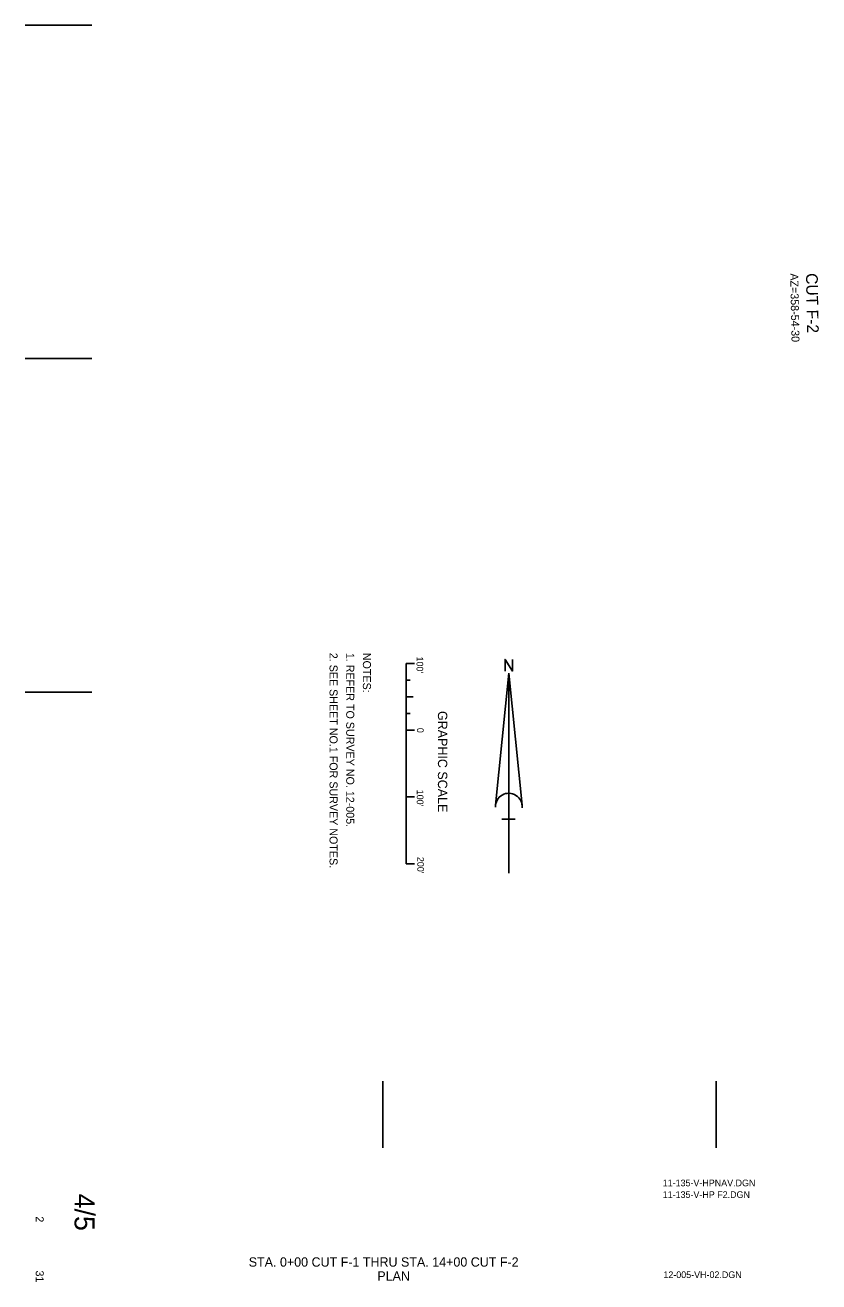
# Model space of a CAD drawing. Extents: x 585464 to 588664, y 1935616 to 1939717.
# Drawn here: x 585464 to 586654, y 1935616 to 1937500 of the extents above; entities that cross this region are included whole.
import ezdxf

# ---------------------------------------------------------------- set-up
doc = ezdxf.new("R2010")
doc.units = 0
for name, color, linetype in [('V-ANNO-DIMS', 7, 'Continuous'), ('V-ANNO-SYMB', 7, 'Continuous'), ('V-ANNO-TEXT', 7, 'Continuous'), ('V-DUCT-MULT', 7, 'Continuous'), ('V-DUCT-MULT-IDEN', 7, 'Continuous')]:
    doc.layers.add(name, color=color, linetype=linetype)

msp = doc.modelspace()

# ---------------------------------------------------------------- linework, layer by layer
at = {"layer": 'V-ANNO-TEXT'}
for p, q in [((585463.7, 1937500), (585563.7, 1937500)), ((585463.7, 1937000), (585563.7, 1937000)), ((585463.7, 1936500), (585563.7, 1936500)), ((586000, 1935917.1), (586000, 1935817.1)), ((586500, 1935917.1), (586500, 1935817.1))]:
    msp.add_line(p, q, dxfattribs=at)
at = {"layer": 'V-DUCT-MULT'}
for p, q in [((586035.3, 1936543), (586035.3, 1936242.9)), ((586035.3, 1936543), (586047.8, 1936542.9)), ((586035.6, 1936518), (586041.3, 1936517.9)), ((586169.1, 1936330.5), (586189, 1936528.5)), ((586189, 1936228.5), (586189, 1936528.5)), ((586208.9, 1936330.5), (586189, 1936528.5)), ((586035.3, 1936493), (586045.5, 1936492.9)), ((586035.6, 1936493), (586041.3, 1936493)), ((586035.6, 1936467.9), (586041.3, 1936467.9)), ((586035.3, 1936442.9), (586047.8, 1936443)), ((586035.3, 1936442.9), (586047.8, 1936443)), ((586035.3, 1936442.9), (586041.3, 1936442.9)), ((586035.3, 1936342.9), (586047.8, 1936342.9)), ((586198.5, 1936309.5), (586178.5, 1936309.5)), ((586035.3, 1936242.9), (586047.8, 1936242.9))]:
    msp.add_line(p, q, dxfattribs=at)
msp.add_lwpolyline([(586183.5, 1936531.7), (586183.5, 1936549.2), (586194.4, 1936531.7), (586194.4, 1936549.2)], dxfattribs=at)
msp.add_arc((586189, 1936328.5), 20, 355.2984, 182.0673, dxfattribs=at)

# ---------------------------------------------------------------- texts
at = {"layer": 'V-ANNO-DIMS'}
for s, height, rotation, p in [('11-135-V-HPNAV.DGN                  ', 10, 360, (586419.8, 1935759.3)), (' 4/5  ', 30, 270, (585537.8, 1935759.4)), ('11-135-V-HP F2.DGN                  ', 10, 360, (586419.8, 1935741.8)), ('  2 ', 12, 270, (585479.6, 1935723.1)), ('       STA. 0+00 CUT F-1 THRU STA. 14+00 CUT F-2       ', 14, 360, (585762.6, 1935638.8)), (' 31 ', 12, 270, (585479.6, 1935637.5)), ('                          PLAN                         ', 14, 360, (585856.6, 1935617.8)), ('12-005-VH-02.DGN                    ', 10, 360, (586420.8, 1935621.7))]:
    msp.add_text(s, height=height, rotation=rotation, dxfattribs=at).set_placement(p)
at = {"layer": 'V-ANNO-SYMB'}
for s, height, p in [('AZ=358-54-30', 12, (586611, 1937127.8)), ('CUT F-2', 17.52, (586634.6, 1937128))]:
    msp.add_text(s, height=height, rotation=271.0918, dxfattribs=at).set_placement(p)
at = {"layer": 'V-DUCT-MULT'}
for s, height, p in [("100'", 10, (586050.6, 1936553.4)), ('GRAPHIC SCALE', 14, (586082.7, 1936471.8)), ('0', 10, (586051.4, 1936446.5)), ("100'", 10, (586051, 1936353.8)), ("200'", 10, (586051.7, 1936253.1))]:
    msp.add_text(s, height=height, rotation=270, dxfattribs=at).set_placement(p)
at = {"layer": 'V-DUCT-MULT-IDEN'}
for s, p in [('2. SEE SHEET NO.1 FOR SURVEY NOTES.', (585920.2, 1936559)), ('1. REFER TO SURVEY NO. 12-005.', (585945.2, 1936559)), ('NOTES:', (585970.2, 1936559))]:
    msp.add_text(s, height=12, rotation=270, dxfattribs=at).set_placement(p)

doc.saveas('drawing.dxf')
